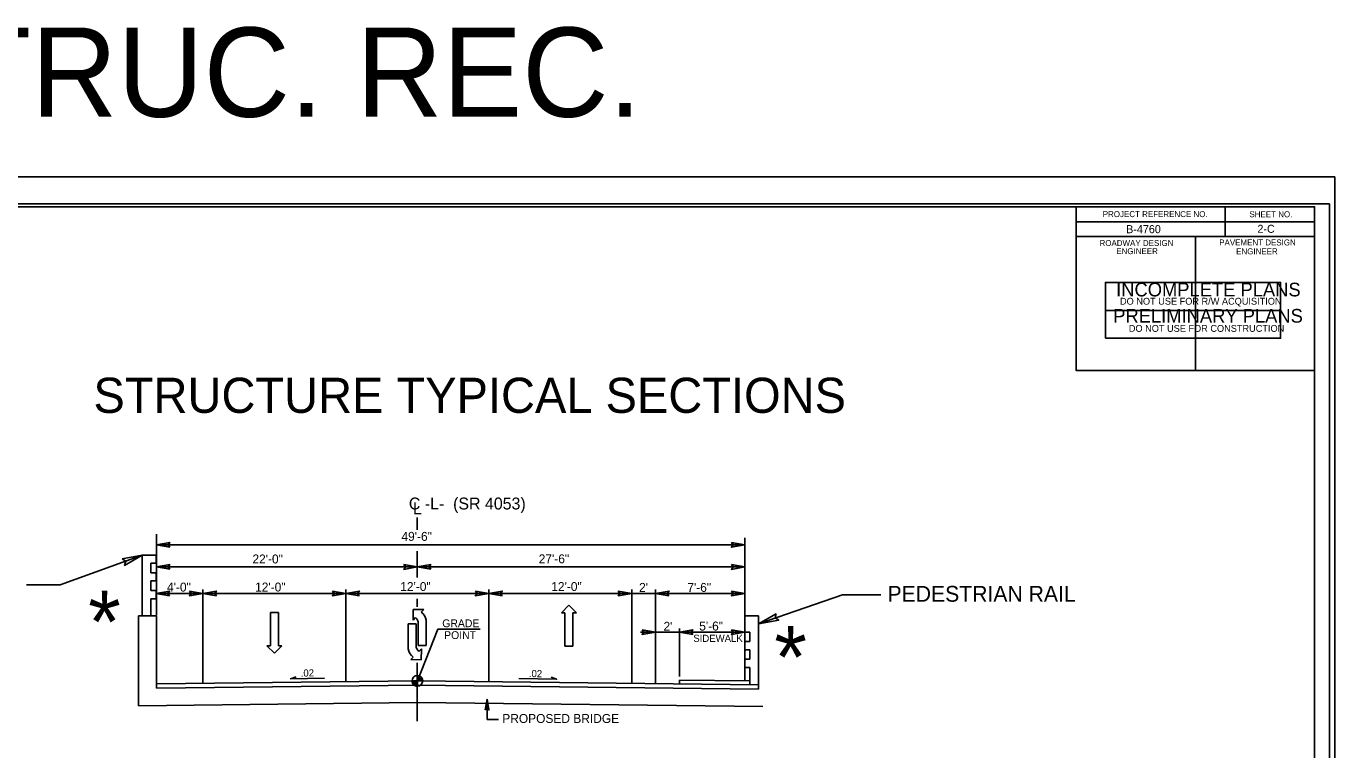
# Model space of a CAD drawing. Extents: x 981824 to 982276, y 44828 to 45204.
# Drawn here: x 981870.7 to 981958.6, y 44965.1 to 45013.7 of the extents above; entities that cross this region are included whole.
import ezdxf

# ---------------------------------------------------------------- set-up
doc = ezdxf.new("R2010")
doc.units = 0
for name, color, linetype in [('Default', 7, 'Continuous'), ('Old_Level_1', 7, 'Continuous'), ('Old_Level_11', 7, 'Continuous'), ('Old_Level_18', 7, 'Continuous'), ('Old_Level_19', 7, 'Continuous'), ('Old_Level_3', 7, 'Continuous'), ('Old_Level_40', 7, 'Continuous'), ('Old_Level_44', 7, 'Continuous'), ('Old_Level_50', 7, 'Continuous'), ('Old_Level_51', 7, 'Continuous'), ('Old_Level_52', 7, 'Continuous'), ('Prop Dimension Text', 7, 'Continuous'), ('Prop Lane Arrow CELL', 7, 'Continuous'), ('Prop Lane Arrow Through CELL', 7, 'Continuous'), ('Prop Terminator CELL', 7, 'Continuous'), ('Sheet Sticker Incomplete CELL', 7, 'Continuous'), ('Sheet Sticker Preliminary CELL', 7, 'Continuous'), ('Typical Terminator CELL', 7, 'Continuous')]:
    doc.layers.add(name, color=color, linetype=linetype)

msp = doc.modelspace()

# ---------------------------------------------------------------- linework, layer by layer
at = {"layer": 'Default'}
for points in [[(981890.728, 44969.892), (981888.458, 44969.839), (981888.824, 44969.978)], [(981903.78, 44969.863), (981906.321, 44969.806), (981905.954, 44969.944)]]:
    msp.add_lwpolyline(points, dxfattribs=at)
at = {"layer": 'Old_Level_1'}
for p, q in [((981958.237, 45001.756), (981958.237, 45001.756)), ((981896.969, 44980.669), (981896.969, 44979.857)), ((981879.44, 44979.549), (981879.44, 44974.108)), ((981918.969, 44979.32), (981918.969, 44969.768)), ((981879.44, 44978.84), (981918.969, 44978.84)), ((981896.969, 44978.416), (981896.969, 44976.645)), ((981872.978, 44976.151), (981878.495, 44978.153)), ((981878.495, 44974.066), (981878.495, 44978.153)), ((981878.495, 44978.153), (981879.42, 44978.153)), ((981879.079, 44977.603), (981879.42, 44977.603)), ((981879.079, 44976.967), (981879.079, 44977.603)), ((981879.42, 44978.153), (981879.42, 44977.603)), ((981879.44, 44977.352), (981896.969, 44977.352)), ((981896.969, 44977.352), (981918.969, 44977.352)), ((981879.079, 44976.967), (981879.42, 44976.967)), ((981879.079, 44976.417), (981879.42, 44976.417)), ((981879.079, 44975.781), (981879.079, 44976.417)), ((981879.42, 44976.967), (981879.42, 44976.417)), ((981879.42, 44976.967), (981879.42, 44976.468)), ((981870.721, 44976.151), (981872.978, 44976.151)), ((981879.079, 44975.781), (981879.42, 44975.781)), ((981879.42, 44975.781), (981879.42, 44975.231)), ((981879.42, 44975.573), (981882.569, 44975.573)), ((981882.569, 44975.835), (981882.569, 44969.534)), ((981882.569, 44975.573), (981892.169, 44975.573)), ((981883.833, 44975.573), (981887.369, 44975.573)), ((981892.169, 44975.835), (981892.169, 44969.648)), ((981892.169, 44975.573), (981901.769, 44975.573)), ((981901.769, 44975.835), (981901.769, 44969.675)), ((981901.769, 44975.573), (981911.369, 44975.573)), ((981911.369, 44975.835), (981911.369, 44969.534)), ((981911.369, 44975.573), (981912.969, 44975.573)), ((981912.969, 44975.835), (981912.969, 44969.534)), ((981912.969, 44975.573), (981917.769, 44975.573)), ((981917.769, 44975.573), (981918.969, 44975.573)), ((981879.079, 44975.219), (981879.42, 44975.219)), ((981879.079, 44974.066), (981879.079, 44975.219)), ((981896.969, 44975.217), (981896.969, 44974.669)), ((981925.536, 44975.478), (981919.894, 44973.528)), ((981928.109, 44975.478), (981925.536, 44975.478)), ((981878.24, 44974.07), (981879.44, 44974.07)), ((981878.24, 44974.07), (981878.24, 44968.028)), ((981879.44, 44969.2), (981879.44, 44974.07)), ((981919.894, 44974.07), (981918.969, 44974.07)), ((981918.969, 44974.07), (981918.969, 44972.978)), ((981919.894, 44969.137), (981919.894, 44974.07)), ((981896.973, 44969.704), (981898.349, 44973.179)), ((981911.968, 44972.978), (981914.569, 44972.978)), ((981914.569, 44973.221), (981914.569, 44970.004)), ((981914.569, 44972.978), (981918.969, 44972.978)), ((981919.31, 44972.978), (981918.969, 44972.978)), ((981919.31, 44972.342), (981919.31, 44972.978)), ((981919.31, 44972.342), (981918.969, 44972.342)), ((981918.969, 44972.342), (981918.969, 44971.792)), ((981918.969, 44972.342), (981918.969, 44971.792)), ((981919.31, 44971.792), (981918.969, 44971.792)), ((981919.31, 44971.156), (981918.969, 44971.156)), ((981918.969, 44971.156), (981918.969, 44970.606)), ((981919.31, 44971.156), (981919.31, 44971.792)), ((981896.969, 44970.918), (981896.969, 44966.988)), ((981919.31, 44970.594), (981918.969, 44970.594)), ((981919.31, 44969.442), (981919.31, 44970.594)), ((981896.969, 44969.704), (981879.44, 44969.497)), ((981896.969, 44969.407), (981879.44, 44969.2)), ((981896.613, 44969.704), (981896.973, 44969.704)), ((981896.969, 44969.704), (981919.894, 44969.434)), ((981896.969, 44969.407), (981919.894, 44969.137)), ((981896.972, 44969.344), (981896.973, 44969.704)), ((981896.973, 44969.704), (981896.972, 44969.344)), ((981896.973, 44969.704), (981896.973, 44970.064)), ((981897.333, 44969.704), (981896.973, 44969.704)), ((981914.569, 44969.746), (981919.31, 44969.691)), ((981914.569, 44969.496), (981914.569, 44969.746)), ((981896.969, 44968.249), (981878.24, 44968.028)), ((981896.969, 44968.249), (981920.169, 44967.975)), ((981901.652, 44968.47), (981901.652, 44967.105)), ((981901.652, 44967.105), (981902.423, 44967.105))]:
    msp.add_line(p, q, dxfattribs=at)
for points in [[(981896.614, 44969.704), (981896.614, 44969.665)], [(981896.621, 44969.704), (981896.621, 44969.623)], [(981896.629, 44969.704), (981896.629, 44969.597)], [(981896.636, 44969.704), (981896.636, 44969.576)], [(981896.643, 44969.704), (981896.643, 44969.559)], [(981896.65, 44969.704), (981896.65, 44969.544)], [(981896.657, 44969.704), (981896.657, 44969.53)], [(981896.665, 44969.704), (981896.665, 44969.517)], [(981896.672, 44969.704), (981896.672, 44969.506)], [(981896.679, 44969.704), (981896.679, 44969.496)], [(981896.686, 44969.704), (981896.686, 44969.486)], [(981896.693, 44969.704), (981896.693, 44969.477)], [(981896.701, 44969.704), (981896.701, 44969.468)], [(981896.708, 44969.704), (981896.708, 44969.46)], [(981896.715, 44969.704), (981896.715, 44969.452)], [(981896.722, 44969.704), (981896.722, 44969.445)], [(981896.729, 44969.704), (981896.729, 44969.439)], [(981896.737, 44969.704), (981896.737, 44969.432)], [(981896.744, 44969.704), (981896.744, 44969.426)], [(981896.751, 44969.704), (981896.751, 44969.42)], [(981896.758, 44969.704), (981896.758, 44969.415)], [(981896.765, 44969.704), (981896.765, 44969.41)], [(981896.773, 44969.704), (981896.773, 44969.405)], [(981896.78, 44969.704), (981896.78, 44969.4)], [(981896.787, 44969.704), (981896.787, 44969.396)], [(981896.794, 44969.704), (981896.794, 44969.392)], [(981896.801, 44969.704), (981896.801, 44969.388)], [(981896.809, 44969.704), (981896.809, 44969.384)], [(981896.816, 44969.704), (981896.816, 44969.38)], [(981896.823, 44969.704), (981896.823, 44969.377)], [(981896.83, 44969.704), (981896.83, 44969.374)], [(981896.837, 44969.704), (981896.837, 44969.371)], [(981896.845, 44969.704), (981896.845, 44969.368)], [(981896.852, 44969.704), (981896.852, 44969.365)], [(981896.859, 44969.704), (981896.859, 44969.363)], [(981896.866, 44969.704), (981896.866, 44969.36)], [(981896.873, 44969.704), (981896.873, 44969.359)], [(981896.881, 44969.704), (981896.881, 44969.356)], [(981896.888, 44969.704), (981896.888, 44969.355)], [(981896.895, 44969.704), (981896.895, 44969.353)], [(981896.902, 44969.704), (981896.902, 44969.352)], [(981896.909, 44969.704), (981896.909, 44969.35)], [(981896.917, 44969.704), (981896.917, 44969.349)], [(981896.924, 44969.704), (981896.924, 44969.348)], [(981896.931, 44969.704), (981896.931, 44969.347)], [(981896.938, 44969.704), (981896.938, 44969.346)], [(981896.945, 44969.704), (981896.945, 44969.345)], [(981896.953, 44969.704), (981896.953, 44969.345)], [(981896.96, 44969.704), (981896.96, 44969.344)], [(981896.967, 44969.704), (981896.967, 44969.344), (981896.967, 44969.344)], [(981896.976, 44970.064), (981896.976, 44970.064), (981896.976, 44969.704)], [(981896.983, 44970.064), (981896.983, 44969.704)], [(981896.99, 44970.064), (981896.99, 44969.704)], [(981896.997, 44970.064), (981896.997, 44969.704)], [(981897.005, 44970.063), (981897.005, 44969.704)], [(981897.012, 44970.062), (981897.012, 44969.704)], [(981897.019, 44970.061), (981897.019, 44969.704)], [(981897.026, 44970.06), (981897.026, 44969.704)], [(981897.033, 44970.06), (981897.033, 44969.704)], [(981897.041, 44970.058), (981897.041, 44969.704)], [(981897.048, 44970.056), (981897.048, 44969.704)], [(981897.055, 44970.055), (981897.055, 44969.704)], [(981897.062, 44970.053), (981897.062, 44969.704)], [(981897.069, 44970.051), (981897.069, 44969.704)], [(981897.077, 44970.049), (981897.077, 44969.704)], [(981897.084, 44970.047), (981897.084, 44969.704)], [(981897.091, 44970.044), (981897.091, 44969.704)], [(981897.098, 44970.042), (981897.098, 44969.704)], [(981897.105, 44970.039), (981897.105, 44969.704)], [(981897.113, 44970.036), (981897.113, 44969.704)], [(981897.12, 44970.032), (981897.12, 44969.704)], [(981897.127, 44970.029), (981897.127, 44969.704)], [(981897.134, 44970.026), (981897.134, 44969.704)], [(981897.141, 44970.022), (981897.141, 44969.704)], [(981897.149, 44970.018), (981897.149, 44969.704)], [(981897.156, 44970.014), (981897.156, 44969.704)], [(981897.163, 44970.01), (981897.163, 44969.704)], [(981897.17, 44970.005), (981897.17, 44969.704)], [(981897.177, 44970), (981897.177, 44969.704)], [(981897.185, 44969.995), (981897.185, 44969.704)], [(981897.192, 44969.99), (981897.192, 44969.704)], [(981897.199, 44969.984), (981897.199, 44969.704)], [(981897.206, 44969.978), (981897.206, 44969.704)], [(981897.213, 44969.972), (981897.213, 44969.704)], [(981897.221, 44969.965), (981897.221, 44969.704)], [(981897.228, 44969.958), (981897.228, 44969.704)], [(981897.235, 44969.951), (981897.235, 44969.704)], [(981897.242, 44969.943), (981897.242, 44969.704)], [(981897.249, 44969.934), (981897.249, 44969.704)], [(981897.257, 44969.925), (981897.257, 44969.704)], [(981897.264, 44969.916), (981897.264, 44969.704)], [(981897.271, 44969.905), (981897.271, 44969.704)], [(981897.278, 44969.894), (981897.278, 44969.704)], [(981897.285, 44969.882), (981897.285, 44969.704)], [(981897.293, 44969.869), (981897.293, 44969.704)], [(981897.3, 44969.854), (981897.3, 44969.704)], [(981897.307, 44969.837), (981897.307, 44969.704)], [(981897.314, 44969.817), (981897.314, 44969.704)], [(981897.321, 44969.792), (981897.321, 44969.704)], [(981897.329, 44969.756), (981897.329, 44969.704)]]:
    msp.add_lwpolyline(points, dxfattribs=at)
msp.add_circle((981896.972, 44969.704), 0.36, dxfattribs=at)
for start, end in [(179.99048, 269.99048), (359.99048, 89.99048)]:
    msp.add_arc((981896.972, 44969.704), 0.36, start, end, dxfattribs=at)
at = {"layer": 'Old_Level_18'}
msp.add_lwpolyline([(981957.237, 45001.552), (981837.237, 45001.552), (981837.237, 44917.552), (981957.237, 44917.552)], close=True, dxfattribs=at)
at = {"layer": 'Old_Level_19'}
for p, q in [((981941.233, 44990.548), (981957.237, 44990.548)), ((981957.237, 44990.548), (981957.237, 44975.174))]:
    msp.add_line(p, q, dxfattribs=at)
at = {"layer": 'Old_Level_3'}
msp.add_line((981898.349, 44973.179), (981901.194, 44973.179), dxfattribs=at)
at = {"layer": 'Old_Level_40'}
for p, q in [((981951.237, 45001.548), (981951.237, 44999.548)), ((981941.233, 45000.548), (981957.237, 45000.548)), ((981949.237, 44999.548), (981949.237, 44990.552))]:
    msp.add_line(p, q, dxfattribs=at)
for points in [[(981941.233, 45001.552), (981957.237, 45001.552), (981957.237, 44999.548), (981941.233, 44999.548)], [(981941.233, 44999.548), (981949.237, 44999.548), (981949.237, 44990.548), (981941.233, 44990.548)], [(981949.237, 44999.548), (981957.237, 44999.548), (981957.237, 44990.548), (981949.237, 44990.548)]]:
    msp.add_lwpolyline(points, close=True, dxfattribs=at)
at = {"layer": 'Old_Level_50'}
msp.add_line((981958.597, 45003.552), (981958.597, 45003.552), dxfattribs=at)
msp.add_lwpolyline([(981958.237, 45001.756), (981824.917, 45001.756), (981824.917, 44917.348), (981958.237, 44917.348)], close=True, dxfattribs=at)
at = {"layer": 'Old_Level_51'}
msp.add_lwpolyline([(981958.597, 45003.552), (981823.877, 45003.552), (981823.877, 44915.552), (981958.597, 44915.552)], close=True, dxfattribs=at)
at = {"layer": 'Old_Level_52'}
msp.add_line((981958.237, 45001.756), (981958.237, 45001.756), dxfattribs=at)
at = {"layer": 'Prop Lane Arrow CELL'}
for p, q in [((981897.395, 44974.499), (981896.683, 44974.499)), ((981896.683, 44974.499), (981896.683, 44973.779)), ((981896.683, 44973.779), (981896.851, 44973.947)), ((981897.227, 44974.323), (981897.395, 44974.499)), ((981896.363, 44973.539), (981896.363, 44971.851)), ((981896.891, 44973.539), (981896.363, 44973.539)), ((981896.891, 44972.075), (981896.891, 44973.539)), ((981897.035, 44973.547), (981897.035, 44972.083)), ((981897.563, 44972.083), (981897.563, 44973.771)), ((981897.035, 44972.083), (981897.563, 44972.083)), ((981896.699, 44971.299), (981896.531, 44971.131)), ((981897.243, 44971.843), (981897.075, 44971.675)), ((981897.235, 44971.123), (981897.243, 44971.843)), ((981896.531, 44971.131), (981897.235, 44971.123))]:
    msp.add_line(p, q, dxfattribs=at)
for centre, radius, start, end in [((981896.509, 44973.551), 0.524, 360, 49.65817), ((981896.73, 44973.647), 0.84, 8.67607, 53.98777), ((981897.412, 44972.074), 0.524, 180, 229.65817), ((981897.191, 44971.978), 0.84, 188.67607, 233.98777)]:
    msp.add_arc(centre, radius, start, end, dxfattribs=at)
at = {"layer": 'Prop Lane Arrow Through CELL'}
for p, q in [((981906.642, 44974.275), (981907.138, 44974.779)), ((981907.138, 44974.779), (981907.65, 44974.275)), ((981887.11, 44972.063), (981887.11, 44974.303)), ((981887.11, 44974.303), (981887.638, 44974.303)), ((981887.638, 44974.303), (981887.638, 44972.063)), ((981906.882, 44974.275), (981906.642, 44974.275)), ((981906.882, 44972.035), (981906.882, 44974.275)), ((981907.65, 44974.275), (981907.41, 44974.275)), ((981907.41, 44974.275), (981907.41, 44972.035)), ((981887.382, 44971.559), (981886.87, 44972.063)), ((981886.87, 44972.063), (981887.11, 44972.063)), ((981887.878, 44972.063), (981887.382, 44971.559)), ((981887.638, 44972.063), (981887.878, 44972.063)), ((981907.41, 44972.035), (981906.882, 44972.035))]:
    msp.add_line(p, q, dxfattribs=at)
at = {"layer": 'Prop Terminator CELL'}
for points in [[(981877.148, 44977.901), (981878.495, 44978.153), (981877.306, 44977.456), (981877.384, 44977.741)], [(981921.083, 44974.208), (981919.894, 44973.528), (981921.251, 44973.767), (981921.007, 44973.933)]]:
    msp.add_lwpolyline(points, close=True, dxfattribs=at)
at = {"layer": 'Sheet Sticker Incomplete CELL'}
msp.add_lwpolyline([(981943.191, 44994.593), (981943.191, 44996.473), (981954.951, 44996.473), (981954.951, 44994.593)], close=True, dxfattribs=at)
at = {"layer": 'Sheet Sticker Preliminary CELL'}
msp.add_lwpolyline([(981943.191, 44992.713), (981943.191, 44994.593), (981954.951, 44994.593), (981954.951, 44992.713)], close=True, dxfattribs=at)
at = {"layer": 'Typical Terminator CELL'}
for points in [[(981880.34, 44978.685), (981879.44, 44978.84), (981880.345, 44979), (981880.23, 44978.84)], [(981918.069, 44978.995), (981918.969, 44978.84), (981918.064, 44978.68), (981918.179, 44978.84)], [(981880.34, 44977.197), (981879.44, 44977.352), (981880.345, 44977.512), (981880.23, 44977.352)], [(981896.069, 44977.507), (981896.969, 44977.352), (981896.064, 44977.192), (981896.179, 44977.352)], [(981897.869, 44977.197), (981896.969, 44977.352), (981897.874, 44977.512), (981897.759, 44977.352)], [(981918.069, 44977.507), (981918.969, 44977.352), (981918.064, 44977.192), (981918.179, 44977.352)], [(981880.32, 44975.418), (981879.42, 44975.573), (981880.325, 44975.733), (981880.21, 44975.573)], [(981881.669, 44975.728), (981882.569, 44975.573), (981881.664, 44975.413), (981881.779, 44975.573)], [(981883.469, 44975.418), (981882.569, 44975.573), (981883.474, 44975.733), (981883.359, 44975.573)], [(981891.269, 44975.728), (981892.169, 44975.573), (981891.264, 44975.413), (981891.379, 44975.573)], [(981893.069, 44975.418), (981892.169, 44975.573), (981893.074, 44975.733), (981892.959, 44975.573)], [(981900.869, 44975.728), (981901.769, 44975.573), (981900.864, 44975.413), (981900.979, 44975.573)], [(981902.669, 44975.418), (981901.769, 44975.573), (981902.674, 44975.733), (981902.559, 44975.573)], [(981910.469, 44975.728), (981911.369, 44975.573), (981910.464, 44975.413), (981910.579, 44975.573)], [(981913.869, 44975.418), (981912.969, 44975.573), (981913.874, 44975.733), (981913.759, 44975.573)], [(981918.069, 44975.728), (981918.969, 44975.573), (981918.064, 44975.413), (981918.179, 44975.573)], [(981912.069, 44973.133), (981912.969, 44972.978), (981912.064, 44972.818), (981912.179, 44972.978)], [(981915.469, 44972.823), (981914.569, 44972.978), (981915.474, 44973.138), (981915.359, 44972.978)], [(981918.069, 44973.133), (981918.969, 44972.978), (981918.064, 44972.818), (981918.179, 44972.978)], [(981901.528, 44967.75), (981901.652, 44968.47), (981901.78, 44967.746), (981901.652, 44967.838)]]:
    msp.add_lwpolyline(points, close=True, dxfattribs=at)

# ---------------------------------------------------------------- texts
at = {"layer": 'Default'}
for s, height, p in [('C -L-  (SR 4053)', 0.8, (981896.401, 44981.214)), ('L', 0.8, (981896.681, 44980.883)), ('49\'-6"', 0.6, (981895.903, 44979.106)), ('22\'-0"', 0.6, (981885.893, 44977.589)), ('27\'-6"', 0.6, (981905.123, 44977.599)), ('4\'-0"', 0.6, (981880.157, 44975.7)), ('12\'-0"', 0.6, (981886.074, 44975.703)), ("2'", 0.6, (981911.864, 44975.678)), ('7\'-6"', 0.6, (981915.103, 44975.678)), ("2'", 0.6, (981913.503, 44973.065)), ('5\'-6"', 0.6, (981915.904, 44973.083)), ('PROPOSED BRIDGE', 0.6, (981902.676, 44966.872))]:
    msp.add_text(s, height=height, dxfattribs=at).set_placement(p)
for rotation, p in [(1.14402, (981889.142, 44969.982)), (358.85598, (981904.457, 44969.957))]:
    msp.add_text('.02  ', height=0.48, rotation=rotation, dxfattribs=at).set_placement(p)
at = {"layer": 'Old_Level_1'}
for s, height, p in [('STRUC. REC.', 6, (981860.776, 45007.594)), ('12\'-0"', 0.6, (981895.822, 44975.737)), ('12\'-0"', 0.6, (981905.967, 44975.737)), ('SIDEWALK', 0.48, (981915.508, 44972.318))]:
    msp.add_text(s, height=height, dxfattribs=at).set_placement(p)
at = {"layer": 'Old_Level_11'}
for s, height, p in [('*', 4.199, (981874.862, 44971.57)), ('PEDESTRIAN RAIL', 1.06299, (981928.551, 44975.017)), ('*', 4.199, (981920.95, 44969.197))]:
    msp.add_text(s, height=height, dxfattribs=at).set_placement(p)
at = {"layer": 'Old_Level_3'}
msp.add_text('STRUCTURE TYPICAL SECTIONS', height=2.3622, dxfattribs=at).set_placement((981875.214, 44987.704))
at = {"layer": 'Old_Level_44'}
for s, height, p in [('PROJECT REFERENCE NO.', 0.40001, (981943.009, 45000.856)), ('SHEET NO.', 0.4, (981952.861, 45000.848)), (' B-4760', 0.54, (981944.379, 44999.776)), ('2-C', 0.54, (981953.397, 44999.8)), ('ROADWAY DESIGN', 0.40001, (981942.793, 44998.916)), ('PAVEMENT DESIGN', 0.40001, (981950.833, 44998.952)), ('ENGINEER', 0.4, (981943.917, 44998.368)), ('ENGINEER', 0.4, (981951.969, 44998.356))]:
    msp.add_text(s, height=height, dxfattribs=at).set_placement(p)
at = {"layer": 'Prop Dimension Text'}
for s, p in [('GRADE', (981898.642, 44973.305)), ('POINT', (981898.769, 44972.51))]:
    msp.add_text(s, height=0.5248, dxfattribs=at).set_placement(p)
at = {"layer": 'Sheet Sticker Incomplete CELL'}
for s, height, p in [('INCOMPLETE PLANS', 0.9216, (981943.907, 44995.529)), ('DO NOT USE FOR R/W ACQUISITION', 0.4608, (981944.167, 44994.973))]:
    msp.add_text(s, height=height, dxfattribs=at).set_placement(p)
at = {"layer": 'Sheet Sticker Preliminary CELL'}
for s, height, p in [('PRELIMINARY PLANS', 0.9216, (981943.711, 44993.765)), ('DO NOT USE FOR CONSTRUCTION', 0.4608, (981944.759, 44993.149))]:
    msp.add_text(s, height=height, dxfattribs=at).set_placement(p)

doc.saveas('drawing.dxf')
